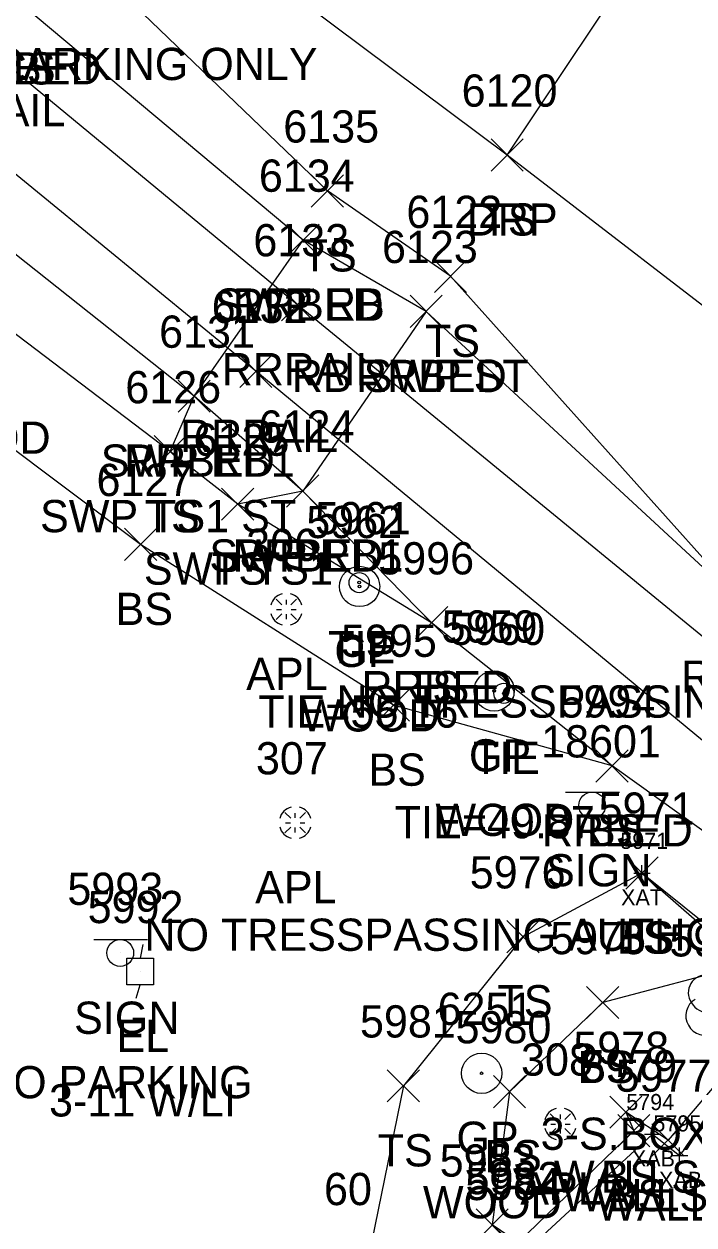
# Model space of a CAD drawing. Extents: x 1618146 to 1620418, y 640749 to 641927.
# Drawn here: x 1619929.8 to 1619971.4, y 641290.7 to 641365.2 of the extents above; entities that cross this region are included whole.
import ezdxf

# ---------------------------------------------------------------- set-up
doc = ezdxf.new("R2010")
doc.units = 0
for name, color, linetype in [('B_A', 7, 'Continuous'), ('B_I', 7, 'Continuous'), ('B_TIC', 7, 'Continuous'), ('BSUBM', 7, 'Continuous'), ('C_A', 7, 'Continuous'), ('C_C', 7, 'Continuous'), ('C_I', 7, 'Continuous'), ('CBP', 7, 'Continuous'), ('Default', 7, 'Continuous'), ('L_A', 7, 'Continuous'), ('L_C', 7, 'Continuous'), ('L_I', 7, 'Continuous'), ('L_TIC', 7, 'Continuous'), ('LELB', 7, 'Continuous'), ('LTD', 7, 'Continuous'), ('LWS', 7, 'Continuous'), ('M_A', 7, 'Continuous'), ('M_I', 7, 'Continuous'), ('R_A', 7, 'Continuous'), ('R_C', 7, 'Continuous'), ('R_I', 7, 'Continuous'), ('R_TIC', 7, 'Continuous'), ('RDP', 7, 'Continuous'), ('RGP', 7, 'Continuous'), ('RR', 7, 'Continuous'), ('RRB', 7, 'Continuous'), ('RSW', 7, 'Continuous'), ('S_A', 7, 'Continuous'), ('S_C', 7, 'Continuous'), ('S_I', 7, 'Continuous'), ('SSGN', 7, 'Continuous'), ('U_A', 7, 'Continuous'), ('U_C', 7, 'Continuous'), ('U_I', 7, 'Continuous'), ('UEPT', 7, 'Continuous')]:
    doc.layers.add(name, color=color, linetype=linetype)

msp = doc.modelspace()

# ---------------------------------------------------------------- linework, layer by layer
at = {"layer": 'B_TIC'}
for p, q in [((1619968.197, 641312.532), (1619968.273, 641312.532)), ((1619968.849, 641296.323), (1619968.924, 641296.323)), ((1619970.535, 641294.997), (1619970.611, 641294.997))]:
    msp.add_line(p, q, dxfattribs=at)
for points in [[(1619968.194, 641312.032), (1619968.194, 641313.032)], [(1619967.694, 641312.532), (1619968.694, 641312.532)], [(1619968.845, 641295.823), (1619968.845, 641296.823)], [(1619968.345, 641296.323), (1619969.345, 641296.323)], [(1619970.532, 641294.497), (1619970.532, 641295.497)], [(1619970.032, 641294.997), (1619971.032, 641294.997)]]:
    msp.add_lwpolyline(points, dxfattribs=at)
at = {"layer": 'BSUBM'}
for points in [[(1619944.713, 641272.679), (1619955.513, 641284.022), (1619968.845, 641296.323), (1619970.532, 641294.997), (1619982.745, 641309.575), (1619989.835, 641318.668), (1619992.379, 641322.295), (1619989.505, 641324.49), (1619988.829, 641324.941), (1619983.751, 641329.259), (1619983.229, 641328.436)], [(1619983.229, 641328.436), (1619983.85, 641328.728), (1619988.897, 641324.455), (1619986.509, 641321.419), (1619977.867, 641310.925), (1619974.814, 641307.218), (1619968.194, 641312.532)]]:
    msp.add_lwpolyline(points, dxfattribs=at)
at = {"layer": 'CBP'}
for centre, radius in [((1619950.636, 641330.556), 0.625), ((1619950.636, 641330.556), 0.0833), ((1619959.622, 641323.687), 0.625), ((1619959.622, 641323.687), 0.0833)]:
    msp.add_circle(centre, radius, dxfattribs=at)
at = {"layer": 'Default'}
for p, q in [((1619945.48, 641329.534), (1619945.834, 641329.18)), ((1619946.117, 641329.197), (1619946.117, 641329.497)), ((1619946.399, 641329.18), (1619946.753, 641329.534)), ((1619945.516, 641328.897), (1619945.816, 641328.897)), ((1619946.416, 641328.897), (1619946.717, 641328.897)), ((1619945.48, 641328.261), (1619945.834, 641328.614)), ((1619946.117, 641328.297), (1619946.117, 641328.597)), ((1619946.399, 641328.614), (1619946.753, 641328.261)), ((1619946.033, 641316.292), (1619946.387, 641315.938)), ((1619946.67, 641315.956), (1619946.67, 641316.256)), ((1619946.952, 641315.938), (1619947.306, 641316.292)), ((1619946.033, 641315.019), (1619946.387, 641315.373)), ((1619946.069, 641315.656), (1619946.37, 641315.656)), ((1619946.67, 641315.056), (1619946.67, 641315.356)), ((1619946.952, 641315.373), (1619947.306, 641315.019)), ((1619946.969, 641315.656), (1619947.27, 641315.656)), ((1619962.491, 641297.596), (1619962.844, 641297.242)), ((1619963.127, 641297.259), (1619963.127, 641297.559)), ((1619963.41, 641297.242), (1619963.764, 641297.596)), ((1619962.491, 641296.323), (1619962.844, 641296.677)), ((1619962.527, 641296.959), (1619962.827, 641296.959)), ((1619963.127, 641296.36), (1619963.127, 641296.659)), ((1619963.41, 641296.677), (1619963.764, 641296.323)), ((1619963.427, 641296.959), (1619963.727, 641296.959))]:
    msp.add_line(p, q, dxfattribs=at)
for centre, start, end in [((1619946.117, 641328.897), 105, 165), ((1619946.117, 641328.897), 15, 75), ((1619946.117, 641328.897), 195, 255), ((1619946.117, 641328.897), 285, 345), ((1619946.67, 641315.656), 105, 165), ((1619946.67, 641315.656), 15, 75), ((1619946.67, 641315.656), 195, 255), ((1619946.67, 641315.656), 285, 345), ((1619963.127, 641296.959), 105, 165), ((1619963.127, 641296.959), 15, 75), ((1619963.127, 641296.959), 195, 255), ((1619963.127, 641296.959), 285, 345)]:
    msp.add_arc(centre, 1, start, end, dxfattribs=at)
at = {"layer": 'L_TIC'}
for points in [[(1619958.824, 641356.091), (1619960.824, 641358.091)], [(1619960.824, 641356.091), (1619958.824, 641358.091)], [(1619947.665, 641353.863), (1619949.665, 641355.863)], [(1619949.665, 641353.863), (1619947.665, 641355.863)], [(1619955.309, 641348.565), (1619957.309, 641350.565)], [(1619957.309, 641348.565), (1619955.309, 641350.565)], [(1619937.914, 641337.684), (1619939.914, 641339.684)], [(1619939.914, 641337.684), (1619937.914, 641339.684)], [(1619942.096, 641334.426), (1619944.096, 641336.426)], [(1619944.096, 641334.426), (1619942.096, 641336.426)], [(1619936.073, 641331.926), (1619938.073, 641333.926)], [(1619938.073, 641331.926), (1619936.073, 641333.926)], [(1619954.137, 641327.065), (1619956.137, 641329.065)], [(1619956.137, 641327.065), (1619954.137, 641329.065)], [(1619951.768, 641321.95), (1619953.768, 641323.95)], [(1619953.768, 641321.95), (1619951.768, 641323.95)], [(1619965.338, 641318.181), (1619967.338, 641320.181)], [(1619967.338, 641318.181), (1619965.338, 641320.181)], [(1619967.194, 641311.532), (1619969.194, 641313.532)], [(1619969.194, 641311.532), (1619967.194, 641313.532)], [(1619967.194, 641311.532), (1619969.194, 641313.532)], [(1619969.194, 641311.532), (1619967.194, 641313.532)], [(1619959.815, 641307.578), (1619961.815, 641309.578)], [(1619961.815, 641307.578), (1619959.815, 641309.578)], [(1619964.755, 641303.498), (1619966.755, 641305.498)], [(1619966.755, 641303.498), (1619964.755, 641305.498)], [(1619952.38, 641298.327), (1619954.38, 641300.327)], [(1619954.38, 641298.327), (1619952.38, 641300.327)], [(1619958.968, 641297.964), (1619960.968, 641299.964)], [(1619960.968, 641297.964), (1619958.968, 641299.964)], [(1619966.19, 641296.692), (1619968.19, 641298.692)], [(1619968.19, 641296.692), (1619966.19, 641298.692)], [(1619966.19, 641296.692), (1619968.19, 641298.692)], [(1619968.19, 641296.692), (1619966.19, 641298.692)], [(1619966.691, 641295.543), (1619968.691, 641297.543)], [(1619968.691, 641295.543), (1619966.691, 641297.543)], [(1619966.691, 641295.543), (1619968.691, 641297.543)], [(1619968.691, 641295.543), (1619966.691, 641297.543)], [(1619968.811, 641294.962), (1619970.811, 641296.962)], [(1619970.811, 641294.962), (1619968.811, 641296.962)], [(1619957.897, 641289.695), (1619959.897, 641291.695)], [(1619959.897, 641289.695), (1619957.897, 641291.695)], [(1619957.897, 641289.695), (1619959.897, 641291.695)], [(1619959.897, 641289.695), (1619957.897, 641291.695)]]:
    msp.add_lwpolyline(points, dxfattribs=at)
at = {"layer": 'LELB'}
for points in [[(1619959.824, 641357.091), (1619968.824, 641370.557), (1619944.084, 641390.011), (1619910.61, 641416.546), (1619871.737, 641447.469), (1619859.446, 641460.524), (1619829.398, 641492.069), (1619805.614, 641511.373), (1619797.779, 641518.218), (1619768.866, 641541.029), (1619773.256, 641565.04), (1619780.173, 641589.774), (1619783.715, 641603.577), (1619764.679, 641610.303)], [(1619966.338, 641319.181), (1619952.768, 641322.95), (1619937.073, 641332.926), (1619914.509, 641349.835), (1619848.675, 641395.565), (1619808.653, 641436.468), (1619772.36, 641467.895)], [(1619974.989, 641328.719), (1619956.309, 641349.565), (1619948.665, 641354.863), (1619932.524, 641370.387), (1619894.799, 641397.938), (1619867.672, 641421.355), (1619823.44, 641453.755)], [(1619938.914, 641338.684), (1619918.332, 641354.28), (1619884.428, 641382.395)], [(1619955.137, 641328.065), (1619943.096, 641335.426)], [(1619968.194, 641312.532), (1619960.815, 641308.578), (1619953.38, 641299.327), (1619949.655, 641281.113)], [(1619968.194, 641312.532), (1619974.679, 641306.85), (1619965.755, 641304.498), (1619959.968, 641298.964), (1619958.897, 641290.695)], [(1619967.19, 641297.692), (1619967.691, 641296.543)]]:
    msp.add_lwpolyline(points, dxfattribs=at)
at = {"layer": 'LTD'}
for centre, major_axis, ratio, start_param, end_param in [((1619972.365, 641305.022), (1.21, -0.512), 0.895232, 1.570796, 4.712389), ((1619972.074, 641303.647), (0.584, -1.042), 0.959034, 3.141593, 6.283185)]:
    msp.add_ellipse(centre, major_axis=major_axis, ratio=ratio, start_param=start_param, end_param=end_param, dxfattribs=at)
at = {"layer": 'LWS'}
for points in [[(1619977.705, 641305.194), (1619969.811, 641295.962), (1619967.19, 641297.692)], [(1619967.691, 641296.543), (1619960.502, 641289.603), (1619958.897, 641290.695), (1619960.48, 641289.237), (1619950.667, 641280.469), (1619949.655, 641281.113), (1619950.01, 641280.086), (1619943.646, 641275.589), (1619936.301, 641276.429), (1619925.244, 641277.538)]]:
    msp.add_lwpolyline(points, dxfattribs=at)
at = {"layer": 'R_TIC'}
for points in [[(1619958.824, 641356.091), (1619960.824, 641358.091)], [(1619960.824, 641356.091), (1619958.824, 641358.091)], [(1619946.152, 641350.81), (1619948.152, 641352.81)], [(1619948.152, 641350.81), (1619946.152, 641352.81)], [(1619946.152, 641350.81), (1619948.152, 641352.81)], [(1619948.152, 641350.81), (1619946.152, 641352.81)], [(1619945.809, 641346.804), (1619947.809, 641348.804)], [(1619947.809, 641346.804), (1619945.809, 641348.804)], [(1619953.794, 641346.387), (1619955.794, 641348.387)], [(1619955.794, 641346.387), (1619953.794, 641348.387)], [(1619953.794, 641346.387), (1619955.794, 641348.387)], [(1619955.794, 641346.387), (1619953.794, 641348.387)], [(1619943.224, 641342.671), (1619945.224, 641344.671)], [(1619945.224, 641342.671), (1619943.224, 641344.671)], [(1619939.391, 641341.129), (1619941.391, 641343.129)], [(1619941.391, 641341.129), (1619939.391, 641343.129)], [(1619939.391, 641341.129), (1619941.391, 641343.129)], [(1619941.391, 641341.129), (1619939.391, 641343.129)], [(1619937.914, 641337.684), (1619939.914, 641339.684)], [(1619939.914, 641337.684), (1619937.914, 641339.684)], [(1619946.134, 641335.24), (1619948.134, 641337.24)], [(1619948.134, 641335.24), (1619946.134, 641337.24)], [(1619946.134, 641335.24), (1619948.134, 641337.24)], [(1619948.134, 641335.24), (1619946.134, 641337.24)], [(1619942.096, 641334.426), (1619944.096, 641336.426)], [(1619944.096, 641334.426), (1619942.096, 641336.426)], [(1619954.137, 641327.065), (1619956.137, 641329.065)], [(1619956.137, 641327.065), (1619954.137, 641329.065)], [(1619965.338, 641318.181), (1619967.338, 641320.181)], [(1619967.338, 641318.181), (1619965.338, 641320.181)]]:
    msp.add_lwpolyline(points, dxfattribs=at)
at = {"layer": 'RDP'}
msp.add_lwpolyline([(1620046.285, 641425.203), (1620030.819, 641393.118), (1620022.197, 641371.362), (1620020.187, 641367.259), (1619996.2, 641331.352), (1619976.433, 641344.297), (1619959.824, 641357.091), (1619936.332, 641374.648), (1619891.262, 641410.402), (1619869.712, 641427.208), (1619819.711, 641475.112), (1619778.808, 641510.608), (1619747.434, 641531.144), (1619747.103, 641530.497), (1619739.147, 641529.243), (1619712.25, 641549.199), (1619714.561, 641555.952)], dxfattribs=at)
at = {"layer": 'RGP'}
for p, q in [((1619950.663, 641330.318), (1619950.663, 641330.318)), ((1619959.02, 641323.834), (1619959.02, 641323.834)), ((1619958.241, 641300.107), (1619958.241, 641300.107))]:
    msp.add_line(p, q, dxfattribs=at)
for centre, radius in [((1619950.663, 641330.318), 1.25), ((1619950.663, 641330.318), 0.0833), ((1619959.02, 641323.834), 1.25), ((1619959.02, 641323.834), 0.0833), ((1619958.241, 641300.107), 1.25), ((1619958.241, 641300.107), 0.0833)]:
    msp.add_circle(centre, radius, dxfattribs=at)
at = {"layer": 'RR'}
for points in [[(1620192.149, 641127.788), (1620168.312, 641155.994), (1620153.359, 641171.838), (1620133.437, 641191.994), (1620110.111, 641213.081), (1620101.472, 641220.641), (1620055.356, 641258.678), (1620021.942, 641286.099), (1619984.199, 641317.184), (1619946.809, 641347.804), (1619927.299, 641363.881), (1619890.892, 641393.618), (1619862.546, 641416.891)], [(1620190.752, 641121.585), (1620164.758, 641152.663), (1620149.827, 641168.387), (1620129.761, 641188.505), (1620106.878, 641209.401), (1620098.404, 641216.876), (1620053.4, 641253.963), (1620018.83, 641282.236), (1619980.557, 641313.635), (1619944.224, 641343.671), (1619924.209, 641360.052), (1619888.22, 641389.605), (1619859.159, 641413.425)]]:
    msp.add_lwpolyline(points, dxfattribs=at)
at = {"layer": 'RRB'}
for points in [[(1619986.509, 641321.419), (1619974.989, 641328.719), (1619954.794, 641347.387), (1619947.152, 641351.81), (1619929.636, 641366.468), (1619892.952, 641395.776), (1619865.639, 641419.736), (1619823.44, 641453.755), (1619786.957, 641483.748), (1619757.137, 641507.969), (1619741.948, 641521.56), (1619734.001, 641527.796), (1619709.515, 641546.084), (1619691.091, 641561.168), (1619661.22, 641583.457)], [(1619977.867, 641310.925), (1619966.338, 641319.181), (1619955.137, 641328.065), (1619947.134, 641336.24), (1619940.391, 641342.129), (1619921.411, 641357.171), (1619886.68, 641385.782), (1619856.812, 641410.874), (1619815.241, 641443.99), (1619779.42, 641474.24), (1619751.613, 641498.168), (1619728.145, 641518.291), (1619703.687, 641537.278), (1619683.355, 641552.45), (1619653.858, 641573.064)]]:
    msp.add_lwpolyline(points, dxfattribs=at)
at = {"layer": 'RSW'}
msp.add_lwpolyline([(1619954.794, 641347.387), (1619947.134, 641336.24), (1619943.096, 641335.426), (1619938.914, 641338.684), (1619940.391, 641342.129), (1619947.152, 641351.81)], dxfattribs=at)
at = {"layer": 'SSGN'}
for p, q in [((1619963.456, 641317.559), (1619966.789, 641317.559)), ((1619965.102, 641316.726), (1619965.102, 641316.726)), ((1619934.157, 641308.408), (1619937.49, 641308.408)), ((1619935.803, 641307.575), (1619935.803, 641307.575))]:
    msp.add_line(p, q, dxfattribs=at)
for centre in [(1619965.102, 641316.726), (1619935.803, 641307.575)]:
    msp.add_circle(centre, 0.833, dxfattribs=at)
at = {"layer": 'UEPT'}
for p, q in [((1619937.208, 641308.093), (1619937.041, 641307.259)), ((1619936.208, 641305.593), (1619936.208, 641307.259)), ((1619936.208, 641307.259), (1619937.875, 641307.259)), ((1619937.875, 641307.259), (1619937.875, 641305.593)), ((1619937.041, 641306.426), (1619937.041, 641306.426)), ((1619937.875, 641305.593), (1619936.208, 641305.593)), ((1619936.791, 641304.759), (1619937.041, 641305.593))]:
    msp.add_line(p, q, dxfattribs=at)

# ---------------------------------------------------------------- texts
at = {"layer": 'B_A'}
for s, p in [('XAT', (1619966.899, 641310.532)), ('XAB', (1619967.566, 641294.323)), ('XAB', (1619969.252, 641292.997))]:
    msp.add_text(s, height=1, dxfattribs=at).set_placement(p)
at = {"layer": 'B_I'}
for s, p in [('5971', (1619966.848, 641314.032)), ('5794', (1619967.216, 641297.823)), ('5795', (1619968.902, 641296.497))]:
    msp.add_text(s, height=1, dxfattribs=at).set_placement(p)
at = {"layer": 'C_A'}
for p in [(1619948.715, 641325.556), (1619957.701, 641318.687)]:
    msp.add_text('TIE', height=2, dxfattribs=at).set_placement(p)
at = {"layer": 'C_C'}
for s, p in [('TIE=55.16', (1619944.377, 641321.556)), ('TIE=49.87', (1619952.85, 641314.687))]:
    msp.add_text(s, height=2, dxfattribs=at).set_placement(p)
at = {"layer": 'C_I'}
for s, p in [('5961', (1619947.896, 641333.556)), ('5960', (1619956.228, 641326.687)), ('60', (1619948.454, 641291.925))]:
    msp.add_text(s, height=2, dxfattribs=at).set_placement(p)
at = {"layer": 'L_A'}
for s, p in [('CS', (1619928.077, 641361.468)), ('TS', (1619958.233, 641352.091)), ('TS', (1619947.074, 641349.863)), ('TS', (1619954.719, 641344.565)), ('TS', (1619937.324, 641333.684)), ('TS', (1619941.506, 641330.426)), ('BS', (1619935.514, 641327.926)), ('TS', (1619953.546, 641323.065)), ('BS', (1619951.209, 641317.95)), ('BS', (1619964.779, 641314.181)), ('TS', (1619966.604, 641307.532)), ('BS', (1619966.635, 641307.532)), ('TS', (1619959.225, 641303.578)), ('BS', (1619964.196, 641299.498)), ('TS', (1619951.79, 641294.327)), ('BS', (1619958.409, 641293.964)), ('WALLS', (1619962.733, 641292.692)), ('BS', (1619965.631, 641292.692)), ('WALLS', (1619963.234, 641291.543)), ('WALLS', (1619965.354, 641290.962)), ('BS', (1619966.132, 641291.543))]:
    msp.add_text(s, height=2, dxfattribs=at).set_placement(p)
at = {"layer": 'L_C'}
msp.add_text('3-S.BOX ELDER', height=2, dxfattribs=at).set_placement((1619961.905, 641295.356))
at = {"layer": 'L_I'}
for s, p in [('6120', (1619956.997, 641360.091)), ('6135', (1619945.925, 641357.863)), ('6122', (1619953.569, 641352.565)), ('6126', (1619936.119, 641341.684)), ('6125', (1619940.356, 641338.426)), ('6127', (1619934.333, 641335.926)), ('5996', (1619951.822, 641331.065)), ('5995', (1619949.508, 641325.95)), ('5994', (1619963.078, 641322.181)), ('5971', (1619965.501, 641315.532)), ('5971', (1619965.501, 641315.532)), ('5976', (1619957.501, 641311.578)), ('5975', (1619962.495, 641307.498)), ('5974', (1619969.897, 641307.356)), ('5981', (1619950.687, 641302.327)), ('5980', (1619956.621, 641301.964)), ('5978', (1619963.93, 641300.692)), ('5978', (1619963.93, 641300.692)), ('5979', (1619964.423, 641299.543)), ('5979', (1619964.423, 641299.543)), ('5977', (1619966.551, 641298.962)), ('5983', (1619955.637, 641293.695)), ('5983', (1619955.637, 641293.695)), ('5982', (1619957.242, 641292.603)), ('5984', (1619957.22, 641292.237))]:
    msp.add_text(s, height=2, dxfattribs=at).set_placement(p)
at = {"layer": 'M_A'}
for p in [(1619943.628, 641323.897), (1619944.181, 641310.656), (1619960.639, 641291.959)]:
    msp.add_text('APL', height=2, dxfattribs=at).set_placement(p)
at = {"layer": 'M_I'}
for s, p in [('306', (1619943.621, 641331.897)), ('307', (1619944.229, 641318.656)), ('308', (1619960.686, 641299.959))]:
    msp.add_text(s, height=2, dxfattribs=at).set_placement(p)
at = {"layer": 'R_A'}
for s, p in [('RRBED', (1619925.282, 641361.468)), ('RRRAIL', (1619922.59, 641358.881)), ('DRP', (1619957.312, 641352.091)), ('SWP RB', (1619941.68, 641346.81)), ('RRBED', (1619942.798, 641346.81)), ('RRRAIL', (1619942.1, 641342.804)), ('RB SWP ST', (1619946.455, 641342.387)), ('RRBED', (1619950.439, 641342.387)), ('RRRAIL', (1619939.515, 641338.671)), ('SWP RB1', (1619934.596, 641337.129)), ('RRBED', (1619936.037, 641337.129)), ('SWP TS1 ST', (1619930.828, 641333.684)), ('SWP RB1', (1619941.339, 641331.24)), ('RRBED', (1619942.78, 641331.24)), ('SWP TS1', (1619937.27, 641330.426)), ('GP', (1619949.096, 641325.318)), ('RRBED', (1619970.634, 641323.719)), ('RRBED', (1619950.783, 641323.065)), ('GP', (1619957.453, 641318.834)), ('RRBED', (1619961.984, 641314.181)), ('GP', (1619956.675, 641295.107))]:
    msp.add_text(s, height=2, dxfattribs=at).set_placement(p)
at = {"layer": 'R_C'}
for p in [(1619922.868, 641338.551), (1619947.017, 641321.318), (1619955.374, 641314.834), (1619954.596, 641291.107)]:
    msp.add_text('WOOD', height=2, dxfattribs=at).set_placement(p)
at = {"layer": 'R_I'}
for s, p in [('6120', (1619956.997, 641360.091)), ('6134', (1619944.412, 641354.81)), ('6134', (1619944.412, 641354.81)), ('6133', (1619944.069, 641350.804)), ('6123', (1619952.054, 641350.387)), ('6123', (1619952.054, 641350.387)), ('6132', (1619941.484, 641346.671)), ('6131', (1619938.218, 641345.129)), ('6131', (1619938.218, 641345.129)), ('6126', (1619936.119, 641341.684)), ('6124', (1619944.394, 641339.24)), ('6124', (1619944.394, 641339.24)), ('6125', (1619940.356, 641338.426)), ('5962', (1619947.356, 641333.318)), ('5996', (1619951.822, 641331.065)), ('5959', (1619955.752, 641326.834)), ('5994', (1619963.078, 641322.181)), ('6251', (1619955.501, 641303.107))]:
    msp.add_text(s, height=2, dxfattribs=at).set_placement(p)
at = {"layer": 'S_A'}
for p in [(1619962.24, 641311.706), (1619932.941, 641302.555)]:
    msp.add_text('SIGN', height=2, dxfattribs=at).set_placement(p)
at = {"layer": 'S_C'}
for s, p in [('PUBLIC PARKING ONLY', (1619917.588, 641361.742)), ('NO TRESSPASSING AUTHORIZED PERS', (1619949.23, 641322.175)), ('NO TRESSPASSING AUTHORIZED PERS', (1619937.304, 641307.706)), ('NO PARKING', (1619927.225, 641298.555))]:
    msp.add_text(s, height=2, dxfattribs=at).set_placement(p)
at = {"layer": 'S_I'}
for s, p in [('18601', (1619961.933, 641319.706)), ('5993', (1619932.524, 641310.555))]:
    msp.add_text(s, height=2, dxfattribs=at).set_placement(p)
at = {"layer": 'U_A'}
msp.add_text('EL', height=2, dxfattribs=at).set_placement((1619935.577, 641301.426))
at = {"layer": 'U_C'}
msp.add_text('3-11 W/LI', height=2, dxfattribs=at).set_placement((1619931.388, 641297.426))
at = {"layer": 'U_I'}
msp.add_text('5992', height=2, dxfattribs=at).set_placement((1619933.782, 641309.426))

doc.saveas('drawing.dxf')
